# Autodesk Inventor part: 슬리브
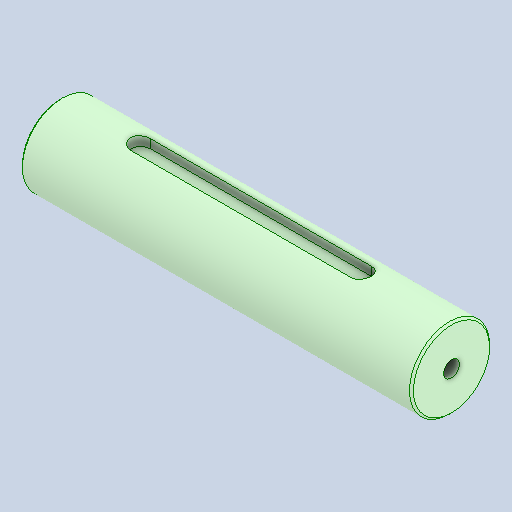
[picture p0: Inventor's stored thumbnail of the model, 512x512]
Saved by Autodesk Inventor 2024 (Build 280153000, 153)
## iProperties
Created: 2024-07
Part Number: 슬리브
Material: 강철, 탄소
Document SubType Name: Modeling
Designer: com
Density: 7.85 g/cm^3
Appearance: 기본값
Author: jhkim
Sending System: Autodesk Inventor 2025
Preprocessor: ST-DEVELOPER v20
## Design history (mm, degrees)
feature "솔리드1"
node "솔리드2"
